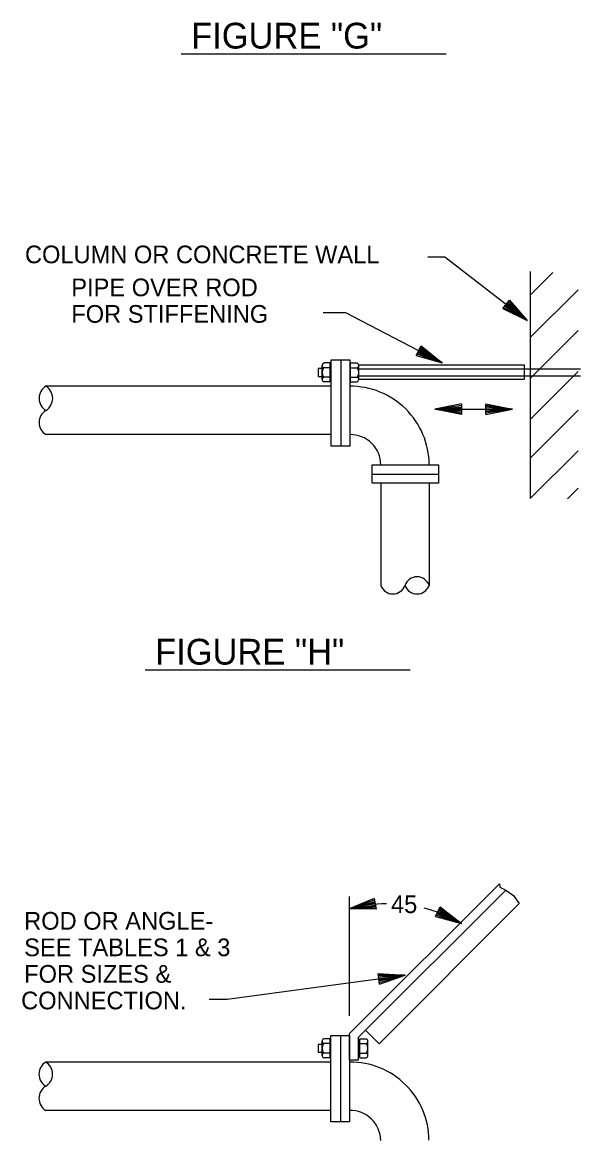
# Model space of a CAD drawing. Extents: x 10040.55 to 10045.84, y 10033.26 to 10035.76.
# Drawn here: x 10041.276 to 10041.592, y 10034.193 to 10034.825 of the extents above; entities that cross this region are included whole.
import ezdxf

# ---------------------------------------------------------------- set-up
doc = ezdxf.new("R2010")
doc.units = 0
doc.layers.add('Level 2', color=7, linetype='Continuous')

msp = doc.modelspace()

# ---------------------------------------------------------------- linework, layer by layer
at = {"layer": 'Level 2'}
for p, q in [((10041.36599, 10034.80732), (10041.51592, 10034.80732)), ((10041.56342, 10034.68422), (10041.56342, 10034.55578)), ((10041.56342, 10034.67086), (10041.57626, 10034.68371)), ((10041.56342, 10034.64688), (10041.59051, 10034.67397)), ((10041.54793, 10034.66335), (10041.55163, 10034.66811)), ((10041.56167, 10034.65651), (10041.5489, 10034.66464)), ((10041.56167, 10034.65651), (10041.54932, 10034.66516)), ((10041.54974, 10034.66572), (10041.56167, 10034.65651)), ((10041.56167, 10034.65651), (10041.55021, 10034.6663)), ((10041.56167, 10034.65651), (10041.55066, 10034.66691)), ((10041.56167, 10034.65651), (10041.55111, 10034.66747)), ((10041.55163, 10034.66811), (10041.56167, 10034.65651)), ((10041.54793, 10034.66335), (10041.56167, 10034.65651)), ((10041.56167, 10034.65651), (10041.5484, 10034.66396)), ((10041.56342, 10034.62382), (10041.59051, 10034.65092)), ((10041.49894, 10034.63681), (10041.50173, 10034.64215)), ((10041.5003, 10034.63946), (10041.51368, 10034.63252)), ((10041.51368, 10034.63252), (10041.50067, 10034.64013)), ((10041.51368, 10034.63252), (10041.501, 10034.64079)), ((10041.51368, 10034.63252), (10041.50134, 10034.64143)), ((10041.50173, 10034.64215), (10041.51368, 10034.63252)), ((10041.45618, 10034.6343), (10041.45618, 10034.58552)), ((10041.49894, 10034.63681), (10041.51368, 10034.63252)), ((10041.51368, 10034.63252), (10041.49929, 10034.63749)), ((10041.51368, 10034.63252), (10041.49966, 10034.63825)), ((10041.51368, 10034.63252), (10041.49999, 10034.63883)), ((10041.44573, 10034.62311), (10041.44573, 10034.63116)), ((10041.45028, 10034.62982), (10041.44654, 10034.62982)), ((10041.45028, 10034.6325), (10041.44657, 10034.6325)), ((10041.45028, 10034.62176), (10041.45028, 10034.6325)), ((10041.46182, 10034.62176), (10041.46182, 10034.6325)), ((10041.46182, 10034.6325), (10041.46553, 10034.6325)), ((10041.46182, 10034.62982), (10041.46556, 10034.62982)), ((10041.46638, 10034.62311), (10041.46638, 10034.63116)), ((10041.46638, 10034.62922), (10041.55998, 10034.62922)), ((10041.55998, 10034.62922), (10041.56341, 10034.62922)), ((10041.56341, 10034.62922), (10041.59198, 10034.62922)), ((10041.56342, 10034.60057), (10041.59051, 10034.62767)), ((10041.45028, 10034.62443), (10041.44654, 10034.62443)), ((10041.45028, 10034.62176), (10041.44654, 10034.62176)), ((10041.46182, 10034.62443), (10041.46556, 10034.62443)), ((10041.46182, 10034.62176), (10041.46556, 10034.62176)), ((10041.46638, 10034.62528), (10041.55998, 10034.62528)), ((10041.55998, 10034.62528), (10041.56344, 10034.62528)), ((10041.56344, 10034.62528), (10041.59198, 10034.62528)), ((10041.45071, 10034.61934), (10041.28935, 10034.61934)), ((10041.52449, 10034.60933), (10041.50944, 10034.60633)), ((10041.50944, 10034.60633), (10041.52449, 10034.60857)), ((10041.50944, 10034.60633), (10041.52451, 10034.60773)), ((10041.52449, 10034.60933), (10041.52448, 10034.60331)), ((10041.55343, 10034.60633), (10041.53836, 10034.60781)), ((10041.53838, 10034.60333), (10041.53839, 10034.60935)), ((10041.55343, 10034.60633), (10041.53838, 10034.60854)), ((10041.53839, 10034.60935), (10041.55343, 10034.60633)), ((10041.50944, 10034.60633), (10041.52449, 10034.60705)), ((10041.5245, 10034.60635), (10041.50944, 10034.60633)), ((10041.50944, 10034.60633), (10041.55343, 10034.60633)), ((10041.52448, 10034.60331), (10041.50944, 10034.60633)), ((10041.50944, 10034.60633), (10041.5245, 10034.60485)), ((10041.50944, 10034.60633), (10041.52449, 10034.60413)), ((10041.50944, 10034.60633), (10041.52449, 10034.60559)), ((10041.55343, 10034.60633), (10041.53835, 10034.60494)), ((10041.53836, 10034.60631), (10041.55343, 10034.60633)), ((10041.55343, 10034.60633), (10041.53838, 10034.60707)), ((10041.53838, 10034.60333), (10041.55343, 10034.60633)), ((10041.55343, 10034.60633), (10041.53838, 10034.60561)), ((10041.55343, 10034.60633), (10041.53838, 10034.60409)), ((10041.56342, 10034.57865), (10041.59051, 10034.60574)), ((10041.45071, 10034.59199), (10041.28935, 10034.59199)), ((10041.56342, 10034.55578), (10041.59051, 10034.58288)), ((10041.47406, 10034.56971), (10041.51161, 10034.56971)), ((10041.47891, 10034.5645), (10041.47891, 10034.50673)), ((10041.50625, 10034.5645), (10041.50625, 10034.50673)), ((10041.58456, 10034.55575), (10041.59051, 10034.5617)), ((10041.3456, 10034.45888), (10041.49553, 10034.45888)), ((10041.46121, 10034.25326), (10041.54598, 10034.338)), ((10041.47517, 10034.32958), (10041.46098, 10034.3237)), ((10041.46109, 10034.26325), (10041.46109, 10034.33078)), ((10041.46631, 10034.25111), (10041.5496, 10034.33438)), ((10041.47517, 10034.32958), (10041.47632, 10034.32367)), ((10041.46098, 10034.3237), (10041.47531, 10034.32883)), ((10041.46098, 10034.3237), (10041.4755, 10034.32801)), ((10041.46098, 10034.3237), (10041.4756, 10034.32735)), ((10041.47575, 10034.32668), (10041.46098, 10034.3237)), ((10041.46098, 10034.3237), (10041.4759, 10034.32592)), ((10041.46098, 10034.3237), (10041.47605, 10034.3252)), ((10041.46098, 10034.3237), (10041.47618, 10034.32449)), ((10041.47632, 10034.32367), (10041.46098, 10034.3237)), ((10041.47794, 10034.24744), (10041.55724, 10034.32674)), ((10041.50978, 10034.31946), (10041.51242, 10034.3249)), ((10041.52463, 10034.31557), (10041.51173, 10034.32351)), ((10041.52463, 10034.31557), (10041.51206, 10034.32415)), ((10041.51242, 10034.3249), (10041.52463, 10034.31557)), ((10041.50978, 10034.31946), (10041.52463, 10034.31557)), ((10041.52463, 10034.31557), (10041.5101, 10034.32017)), ((10041.52463, 10034.31557), (10041.51046, 10034.32093)), ((10041.52463, 10034.31557), (10041.51077, 10034.32151)), ((10041.51107, 10034.32216), (10041.52463, 10034.31557)), ((10041.52463, 10034.31557), (10041.51141, 10034.32283)), ((10041.4781, 10034.28121), (10041.47732, 10034.28719)), ((10041.47732, 10034.28719), (10041.49264, 10034.28618)), ((10041.49264, 10034.28618), (10041.47742, 10034.28638)), ((10041.49264, 10034.28618), (10041.47751, 10034.28566)), ((10041.49264, 10034.28618), (10041.47761, 10034.28492)), ((10041.47771, 10034.28417), (10041.49264, 10034.28618)), ((10041.49264, 10034.28618), (10041.47781, 10034.28347)), ((10041.49264, 10034.28618), (10041.47788, 10034.2828)), ((10041.49264, 10034.28618), (10041.47801, 10034.28197)), ((10041.4781, 10034.28121), (10041.49264, 10034.28618)), ((10041.47795, 10034.24744), (10041.47029, 10034.25509)), ((10041.44564, 10034.24091), (10041.44564, 10034.24895)), ((10041.45019, 10034.24761), (10041.44645, 10034.24761)), ((10041.45019, 10034.25029), (10041.44648, 10034.25029)), ((10041.45019, 10034.23955), (10041.45019, 10034.25029)), ((10041.45608, 10034.25209), (10041.45608, 10034.20331)), ((10041.46121, 10034.23835), (10041.46121, 10034.25326)), ((10041.46631, 10034.23835), (10041.46631, 10034.25111)), ((10041.46699, 10034.23955), (10041.46699, 10034.25029)), ((10041.46699, 10034.25029), (10041.4707, 10034.25029)), ((10041.46699, 10034.24761), (10041.47073, 10034.24761)), ((10041.47154, 10034.24091), (10041.47154, 10034.24895)), ((10041.45019, 10034.24222), (10041.44645, 10034.24222)), ((10041.46699, 10034.24222), (10041.47073, 10034.24222)), ((10041.45061, 10034.23714), (10041.28926, 10034.23714)), ((10041.45019, 10034.23955), (10041.44645, 10034.23955)), ((10041.46121, 10034.23835), (10041.4663, 10034.23835)), ((10041.46699, 10034.23955), (10041.47073, 10034.23955)), ((10041.45061, 10034.20978), (10041.28926, 10034.20978))]:
    msp.add_line(p, q, dxfattribs=at)
for points in [[(10041.50543, 10034.6925), (10041.51518, 10034.6925), (10041.56167, 10034.65651)], [(10041.4462, 10034.66101), (10041.45895, 10034.66101), (10041.51368, 10034.63252)], [(10041.44571, 10034.62934), (10041.44345, 10034.62934), (10041.44345, 10034.62494), (10041.44571, 10034.62494)], [(10041.46638, 10034.63142), (10041.56001, 10034.63142), (10041.56001, 10034.62322), (10041.46638, 10034.62322)], [(10041.54598, 10034.338), (10041.54633, 10034.33609), (10041.5496, 10034.33438), (10041.55406, 10034.33138), (10041.55724, 10034.32674)], [(10041.38184, 10034.27275), (10041.39192, 10034.27275), (10041.49264, 10034.28618)], [(10041.44561, 10034.24714), (10041.44335, 10034.24714), (10041.44335, 10034.24273), (10041.44561, 10034.24273)]]:
    msp.add_lwpolyline(points, dxfattribs=at)
for points in [[(10041.4613, 10034.58552), (10041.45071, 10034.58552), (10041.45071, 10034.6343), (10041.4613, 10034.6343)], [(10041.51161, 10034.5645), (10041.47406, 10034.5645), (10041.47406, 10034.57485), (10041.51161, 10034.57485)], [(10041.46121, 10034.20331), (10041.45061, 10034.20331), (10041.45061, 10034.25209), (10041.46121, 10034.25209)]]:
    msp.add_lwpolyline(points, close=True, dxfattribs=at)
for centre, radius, start, end in [((10041.45069, 10034.62712), 0.00496, 147.00616, 212.94298), ((10041.44724, 10034.63115), 0.0015, 116.78269, 241.8391), ((10041.46486, 10034.63115), 0.0015, 298.1609, 63.21731), ((10041.46141, 10034.62712), 0.00496, 327.05703, 32.99384), ((10041.44723, 10034.6231), 0.0015, 117.8877, 242.03419), ((10041.46487, 10034.6231), 0.0015, 297.96581, 62.1123), ((10041.29349, 10034.61251), 0.00799, 121.17154, 238.82938), ((10041.28522, 10034.61251), 0.00799, 301.17062, 58.82846), ((10041.46169, 10034.57478), 0.04456, 0.36422, 90.5045), ((10041.29349, 10034.59883), 0.00799, 121.17062, 238.82846), ((10041.46169, 10034.57478), 0.01721, 0.36665, 91.08459), ((10041.48574, 10034.50909), 0.00723, 199.09589, 340.90477), ((10041.49941, 10034.50436), 0.00723, 19.09589, 160.90477), ((10041.49941, 10034.50909), 0.00723, 199.09523, 340.90411), ((10041.48309, 10034.24365), 0.08305, 90.63148, 105.44174), ((10041.48309, 10034.24365), 0.08305, 60.00147, 75.77286), ((10041.4506, 10034.24491), 0.00496, 147.00616, 212.94298), ((10041.44715, 10034.24894), 0.0015, 116.78269, 241.8391), ((10041.47003, 10034.24894), 0.0015, 298.1609, 63.21731), ((10041.46658, 10034.24491), 0.00496, 327.05703, 32.99384), ((10041.44714, 10034.24089), 0.0015, 117.8877, 242.03419), ((10041.47004, 10034.24089), 0.0015, 297.96581, 62.1123), ((10041.2934, 10034.2303), 0.00799, 121.17154, 238.82938), ((10041.28512, 10034.2303), 0.00799, 301.17062, 58.82846), ((10041.4616, 10034.19257), 0.04456, 0.36422, 90.5045), ((10041.2934, 10034.21662), 0.00799, 121.17062, 238.82846), ((10041.4616, 10034.19257), 0.01721, 0.36665, 91.08459)]:
    msp.add_arc(centre, radius, start, end, dxfattribs=at)

# ---------------------------------------------------------------- texts
for s, height, p in [('FIGURE "G"', 0.014583, (10041.37156, 10034.81035)), ('COLUMN OR CONCRETE WALL', 0.01, (10041.27752, 10034.68891)), ('PIPE OVER ROD', 0.01, (10041.30374, 10034.67026)), ('FOR STIFFENING', 0.01, (10041.30374, 10034.65526)), ('FIGURE "H"', 0.014583, (10041.35118, 10034.46191)), ('45', 0.01, (10041.48464, 10034.32138)), ('ROD OR ANGLE-', 0.01, (10041.27707, 10034.312)), ('SEE TABLES 1 & 3', 0.01, (10041.27707, 10034.297)), ('FOR SIZES &', 0.01, (10041.27707, 10034.282)), ('CONNECTION.', 0.01, (10041.27535, 10034.26696))]:
    msp.add_text(s, height=height, dxfattribs=at).set_placement(p)

doc.saveas('drawing.dxf')
